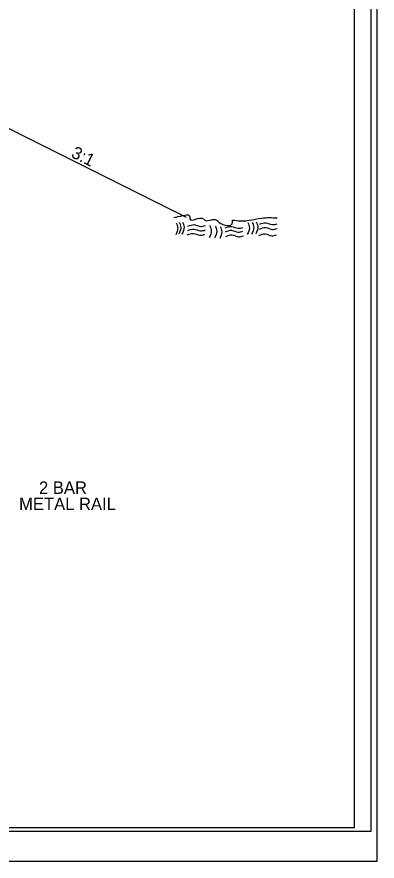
# Model space of a CAD drawing. Extents: x 1734085 to 1734267, y 541107 to 541226.
# Drawn here: x 1734237.5 to 1734266.5, y 541107.1 to 541175.2 of the extents above; entities that cross this region are included whole.
import ezdxf

# ---------------------------------------------------------------- set-up
doc = ezdxf.new("R2010")
doc.units = 0
for name, color, linetype in [('Old_Level_2', 7, 'Continuous'), ('Prop Dimension', 7, 'Continuous'), ('Sheet Cutting Line CELL', 7, 'Continuous'), ('Sheet Plot Border Inside CELL', 7, 'Continuous'), ('Sheet Plot Border Outside CELL', 7, 'Continuous'), ('Sheet Typical CELL', 7, 'Continuous'), ('Typical Slope Point Local CELL', 7, 'Continuous')]:
    doc.layers.add(name, color=color, linetype=linetype)

msp = doc.modelspace()

# ---------------------------------------------------------------- linework, layer by layer
at = {"layer": 'Old_Level_2'}
for points in [[(1734250.132, 541158.995), (1734250.318, 541159.018), (1734251.415, 541159.03), (1734251.417, 541158.874), (1734252.513, 541158.887), (1734252.671, 541158.732), (1734252.828, 541158.734), (1734253.611, 541158.743), (1734253.77, 541158.588), (1734254.866, 541158.6), (1734254.864, 541158.757), (1734255.021, 541158.759), (1734257.212, 541158.941), (1734258.46, 541158.955)], [(1734250.315, 541158.557), (1734250.443, 541158.137), (1734250.274, 541157.591)], [(1734250.56, 541158.594), (1734250.688, 541158.175), (1734250.519, 541157.629)], [(1734250.823, 541158.615), (1734250.951, 541158.195), (1734250.782, 541157.649)], [(1734251.257, 541158.278), (1734251.764, 541158.407), (1734252.292, 541158.255), (1734252.677, 541158.329)], [(1734253.019, 541158.342), (1734253.147, 541157.923), (1734252.978, 541157.377)], [(1734253.459, 541158.295), (1734253.586, 541157.875), (1734253.417, 541157.329)], [(1734253.863, 541158.247), (1734253.99, 541157.827), (1734253.821, 541157.281)], [(1734254.276, 541158.137), (1734254.784, 541158.266), (1734255.312, 541158.114), (1734255.697, 541158.189)], [(1734256.087, 541158.571), (1734256.215, 541158.151), (1734256.046, 541157.605)], [(1734256.438, 541158.592), (1734256.565, 541158.173), (1734256.396, 541157.627)], [(1734256.771, 541158.631), (1734256.898, 541158.212), (1734256.729, 541157.666)], [(1734257.032, 541158.046), (1734257.539, 541158.175), (1734258.067, 541158.023), (1734258.452, 541158.098)], [(1734257.045, 541158.433), (1734257.552, 541158.561), (1734258.08, 541158.41), (1734258.466, 541158.484)], [(1734251.195, 541157.575), (1734251.702, 541157.704), (1734252.23, 541157.552), (1734252.615, 541157.627)], [(1734251.243, 541157.927), (1734251.751, 541158.055), (1734252.279, 541157.904), (1734252.664, 541157.978)], [(1734254.28, 541157.822), (1734254.787, 541157.95), (1734255.315, 541157.798), (1734255.7, 541157.873)], [(1734254.319, 541157.454), (1734254.827, 541157.582), (1734255.355, 541157.431), (1734255.74, 541157.505)], [(1734256.985, 541157.537), (1734257.493, 541157.666), (1734258.021, 541157.514), (1734258.406, 541157.589)]]:
    msp.add_spline(points, degree=3, dxfattribs=at)
at = {"layer": 'Sheet Cutting Line CELL'}
msp.add_line((1734084.641, 541107.075), (1734266.513, 541107.075), dxfattribs=at)
at = {"layer": 'Sheet Plot Border Inside CELL'}
msp.add_lwpolyline([(1734266.027, 541223.451), (1734086.045, 541223.451), (1734086.045, 541109.5), (1734266.027, 541109.5)], close=True, dxfattribs=at)
at = {"layer": 'Sheet Plot Border Outside CELL'}
msp.add_lwpolyline([(1734266.513, 541225.875), (1734084.641, 541225.875), (1734084.641, 541107.075), (1734266.513, 541107.075)], close=True, dxfattribs=at)
at = {"layer": 'Sheet Typical CELL'}
msp.add_lwpolyline([(1734264.677, 541223.175), (1734102.677, 541223.175), (1734102.677, 541109.775), (1734264.677, 541109.775)], close=True, dxfattribs=at)
at = {"layer": 'Typical Slope Point Local CELL'}
msp.add_line((1734251.137, 541158.975), (1734236.14, 541166.474), dxfattribs=at)

# ---------------------------------------------------------------- texts
at = {"layer": 'Prop Dimension'}
for s, p in [('2 BAR', (1734239.257, 541136.695)), ('METAL RAIL', (1734237.652, 541135.384))]:
    msp.add_text(s, height=1, dxfattribs=at).set_placement(p)
at = {"layer": 'Typical Slope Point Local CELL'}
msp.add_text('3:1', height=1, rotation=333.43495, dxfattribs=at).set_placement((1734241.775, 541163.886))

doc.saveas('drawing.dxf')
